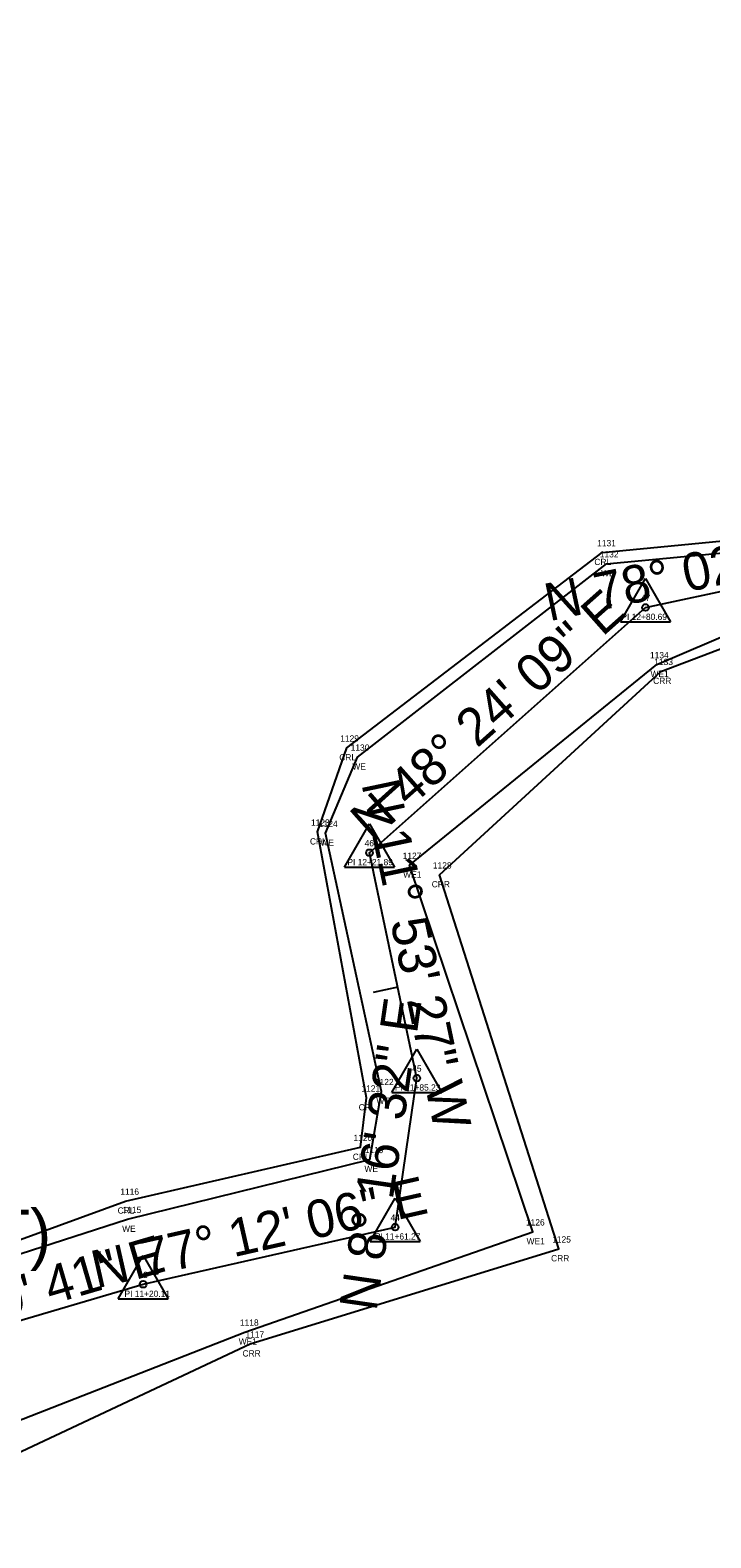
# Model space of a CAD drawing. Extents: x 2445178 to 2446205, y 790762 to 792372.
# Drawn here: x 2445811.8 to 2445920.2, y 791778.3 to 792018.2 of the extents above; entities that cross this region are included whole.
import ezdxf

# ---------------------------------------------------------------- set-up
doc = ezdxf.new("R2010")
doc.units = 0
for name, color, linetype in [('RD_EX_H2O', 7, 'Continuous'), ('RD_EX_H2O_txCode', 7, 'Continuous'), ('RD_HC_Cl', 7, 'Continuous'), ('RD_HC_Data', 7, 'Continuous'), ('RD_HC_Data_Tic', 7, 'Continuous'), ('RD_HC_txCode', 7, 'Continuous'), ('RD_SMD_Locator', 7, 'Continuous')]:
    doc.layers.add(name, color=color, linetype=linetype)

msp = doc.modelspace()

# ---------------------------------------------------------------- linework, layer by layer
at = {"layer": 'RD_EX_H2O'}
for points in [[(2445749.98, 791821.69), (2445784.5, 791816.33), (2445784.5, 791816.33), (2445826.97, 791831.85), (2445864.4, 791840.41), (2445865.35, 791848.28), (2445857.59, 791890.6), (2445862.25, 791903.98), (2445902.88, 791935.07), (2445928.13, 791937.54), (2445982.7, 791973.27), (2446006.36, 791974.66), (2446055.29, 791944.59), (2446112.86, 791944.82), (2446116.06, 791949.26), (2446125.53, 791975.87), (2446156.76, 791972.15), (2446187.24, 792018.21)], [(2445757.3, 791817.48), (2445784.85, 791815.29), (2445827.3, 791828.95), (2445865.88, 791838.48), (2445867.77, 791849.3), (2445858.86, 791890.39), (2445863.96, 791902.52), (2445903.58, 791933.29), (2445928.32, 791935.62), (2445983.75, 791971.59), (2446005.28, 791972.74), (2446055.03, 791943.12), (2446113.69, 791943.23), (2446117.06, 791949.31), (2446126.55, 791974.16), (2446158.67, 791970.49), (2446188.67, 792015.57)], [(2445748.32, 791780.49), (2445788.24, 791788.44), (2445846, 791811.01), (2445891.85, 791826.96), (2445872.2, 791885.31), (2445911.58, 791917.24), (2445942.41, 791930.41), (2445989.95, 791963.2), (2446004.43, 791957.67), (2446037.13, 791928.19), (2446062.94, 791924.63), (2446122.42, 791925.89), (2446133.98, 791956.62), (2446163.05, 791958.48), (2446202.11, 792005.16)], [(2445746.88, 791778.25), (2445790.91, 791782.86), (2445846.87, 791809.11), (2445896.01, 791824.25), (2445877, 791883.78), (2445912.26, 791916.16), (2445942.78, 791927.77), (2445991.6, 791962.06), (2446003.69, 791956.06), (2446036.32, 791927.07), (2446060.96, 791923.67), (2446122.97, 791923.97), (2446134.24, 791956.18), (2446163.21, 791958.01), (2446202.51, 792004.24)]]:
    msp.add_lwpolyline(points, dxfattribs=at)
at = {"layer": 'RD_HC_Cl'}
for p, q in [((2445909.8, 791926.34), (2445934.28, 791931.53)), ((2445865.83, 791887.3), (2445909.8, 791926.34)), ((2445873.38, 791851.43), (2445865.83, 791887.3)), ((2445869.94, 791827.72), (2445873.38, 791851.43)), ((2445829.8, 791818.6), (2445869.94, 791827.72)), ((2445787.35, 791806.17), (2445829.8, 791818.6))]:
    msp.add_line(p, q, dxfattribs=at)
at = {"layer": 'RD_HC_Data'}
for p, q in [((2445905.83, 791924.05), (2445909.8, 791930.93)), ((2445909.8, 791930.93), (2445913.77, 791924.05)), ((2445905.83, 791924.05), (2445913.77, 791924.05)), ((2445861.86, 791885.01), (2445865.83, 791891.89)), ((2445865.83, 791891.89), (2445869.8, 791885.01)), ((2445861.86, 791885.01), (2445869.8, 791885.01)), ((2445869.41, 791849.13), (2445873.39, 791856.01)), ((2445873.39, 791856.01), (2445877.35, 791849.13)), ((2445869.41, 791849.13), (2445877.35, 791849.13)), ((2445865.97, 791825.43), (2445869.94, 791832.31)), ((2445869.94, 791832.31), (2445873.91, 791825.43)), ((2445865.97, 791825.43), (2445873.91, 791825.43)), ((2445825.83, 791816.31), (2445829.8, 791823.19)), ((2445829.8, 791823.19), (2445833.77, 791816.31)), ((2445825.83, 791816.31), (2445833.77, 791816.31))]:
    msp.add_line(p, q, dxfattribs=at)
for centre in [(2445909.8, 791926.34), (2445865.83, 791887.3), (2445873.38, 791851.43), (2445869.94, 791827.72), (2445829.8, 791818.6)]:
    msp.add_circle(centre, 0.529, dxfattribs=at)
at = {"layer": 'RD_HC_Data_Tic'}
msp.add_line((2445870.34, 791865.88), (2445866.43, 791865.06), dxfattribs=at)
at = {"layer": 'RD_SMD_Locator'}
for centre in [(2445902.88, 791935.07), (2445903.58, 791933.29), (2445909.8, 791926.34), (2445911.58, 791917.24), (2445912.26, 791916.16), (2445862.25, 791903.98), (2445863.96, 791902.52), (2445857.59, 791890.6), (2445858.86, 791890.39), (2445865.83, 791887.3), (2445872.2, 791885.31), (2445877, 791883.78), (2445867.77, 791849.3), (2445873.38, 791851.43), (2445865.35, 791848.28), (2445864.4, 791840.41), (2445865.88, 791838.48), (2445826.97, 791831.85), (2445827.3, 791828.95), (2445869.94, 791827.72), (2445891.85, 791826.96), (2445896.01, 791824.25), (2445829.8, 791818.6), (2445846, 791811.01), (2445846.87, 791809.11)]:
    msp.add_circle(centre, 0.001, dxfattribs=at)

# ---------------------------------------------------------------- texts
at = {"layer": 'RD_EX_H2O_txCode'}
for s, p in [('1131', (2445902.1, 791936.07)), ('CRL', (2445901.65, 791933.07)), ('1132', (2445902.52, 791934.29)), ('WE', (2445902.74, 791931.29)), ('1134', (2445910.51, 791918.24)), ('1133', (2445911.19, 791917.16)), ('WE1', (2445910.59, 791915.24)), ('CRR', (2445911.01, 791914.16)), ('1129', (2445861.19, 791904.98)), ('1130', (2445862.85, 791903.52)), ('CRL', (2445861.03, 791901.98)), ('WE', (2445863.12, 791900.52)), ('1123', (2445856.53, 791891.6)), ('1124', (2445857.8, 791891.39)), ('CRL', (2445856.36, 791888.6)), ('WE', (2445858.03, 791888.39)), ('1127', (2445871.13, 791886.31)), ('1128', (2445875.94, 791884.78)), ('WE1', (2445871.21, 791883.31)), ('CRR', (2445875.75, 791881.78)), ('1121', (2445864.57, 791849.28)), ('1122', (2445866.71, 791850.3)), ('CRL', (2445864.12, 791846.28)), ('WE', (2445866.94, 791847.3)), ('1120', (2445863.3, 791841.41)), ('1119', (2445865.1, 791839.48)), ('CRL', (2445863.18, 791838.41)), ('WE', (2445865.04, 791836.48)), ('1116', (2445826.17, 791832.85)), ('CRL', (2445825.74, 791829.85)), ('1115', (2445826.52, 791829.95)), ('WE', (2445826.46, 791826.95)), ('1126', (2445890.76, 791827.96)), ('WE1', (2445890.86, 791824.96)), ('1125', (2445894.94, 791825.25)), ('CRR', (2445894.76, 791822.25)), ('1118', (2445845.22, 791812.01)), ('1117', (2445846.09, 791810.11)), ('WE1', (2445845.02, 791809.01)), ('CRR', (2445845.62, 791807.11))]:
    msp.add_text(s, height=1, dxfattribs=at).set_placement(p)
at = {"layer": 'RD_HC_Data'}
for s, rotation, p in [('N 78%%d 02\' 06" E', 11.965, (2445894.46, 791924.11)), ('N 48%%d 24\' 09" E', 41.5976, (2445866.23, 791889)), ('N 11%%d 53\' 27" W', 281.8909, (2445864.54, 791898.26)), ('N 8%%d 16\' 32" E', 81.7244, (2445866.96, 791814.21)), ('N 77%%d 12\' 06" E', 12.7985, (2445822.36, 791817.94)), ('N 73%%d 40\' 41" E', 16.322, (2445781.44, 791805.48))]:
    msp.add_text(s, height=6, rotation=rotation, dxfattribs=at).set_placement(p)
msp.add_text('    = 15%%d 29\' 27" (RT)', height=7.5, dxfattribs=at).set_placement((2445724, 791823))
at = {"layer": 'RD_HC_txCode'}
for s, p in [('47', (2445909.07, 791927.34)), ('PI 12+80.69', (2445905.96, 791924.34)), ('46', (2445865.07, 791888.3)), ('PI 12+21.89', (2445862.33, 791885.3)), ('45', (2445872.65, 791852.43)), ('PI 11+85.23', (2445869.89, 791849.43)), ('44', (2445869.2, 791828.72)), ('PI 11+61.27', (2445866.7, 791825.72)), ('43', (2445829.07, 791819.6)), ('PI 11+20.11', (2445826.83, 791816.6))]:
    msp.add_text(s, height=1, dxfattribs=at).set_placement(p)

doc.saveas('drawing.dxf')
